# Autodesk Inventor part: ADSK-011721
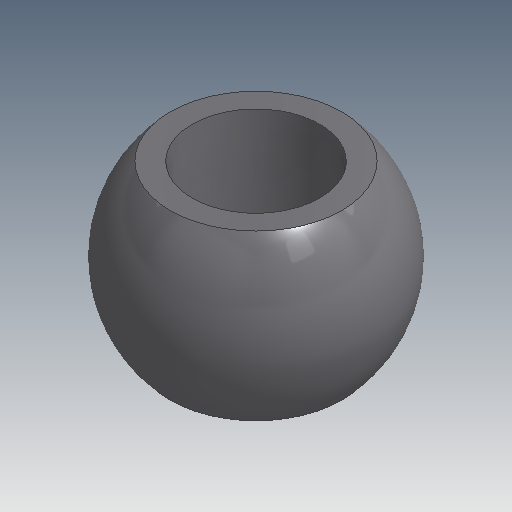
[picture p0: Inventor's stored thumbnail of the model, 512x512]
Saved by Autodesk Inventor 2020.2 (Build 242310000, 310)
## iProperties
Created: 1999-12
Part Number: ADSK-011721
Material: Acier (alliage faible hypertrempé)
Document SubType Name: Modeling
Designer: gpurviance
Density: 7.84 g/cm^3
Appearance: Metal-Steel(Polish)
Mass: 20.6192 g
Surface Area: 15.795 cm^2
Volume: 2.63 cm^3
Control State: 0
Checked Out: False
Last Check In By: gpurviance
Last Check In Date: 1999-12-17
Master: False
Shininess: 0.0
Length Units: 11272
Angle Units: 11279
Time Units: 11290
Mass Units: 11286
Length Display Precision: 3
Angle Display Precision: 2
Compacted: True
Dimensions: 0,6x0,8x0,8 in
Mass: 0,045 lb
VLT_Material: Acier (alliage faible hypertrempé)
Density: 0.0
Volumn: 0.0
Area: 0.0
PropertySet Name: Model Information
Author: gpurviance
Revision Number: -
Title: ADSK-011721
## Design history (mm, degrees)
node "Revolution1" dims "d6" = 90 deg
node "Solide1"
node "Corps solides"
node "Corps surfaciques"
sketch "Sketch1"
  geometry: L1 (0, 14.287)-(0, -15.875) reference; L2 (0, -0.794)-(12.7, -0.794) reference; L3 (5.556, 6.35)-(7.446, 6.35); L4 (5.556, -7.938)-(7.446, -7.938); L5 (5.556, 6.35)-(5.556, -7.938); A1 r 10.319 centre (0, -0.794) between (7.446, -7.938) and (7.446, 6.35)
  constraints: 10 end point, 2 perpendicular, 2 point on circle, 2 vertical, 1 centre point, 1 coincident, 1 horizontal, 1 parallel
  dimensions: "d1" = 14.2875 distance between parallel lines of L4 L3; "d3" = 7.14375 distance between parallel lines of L2 L4 (= 0.5 x d1); "d4" = 5.55625 distance between parallel lines of L5 L1; "d5" = 10.31875 radius of A1
